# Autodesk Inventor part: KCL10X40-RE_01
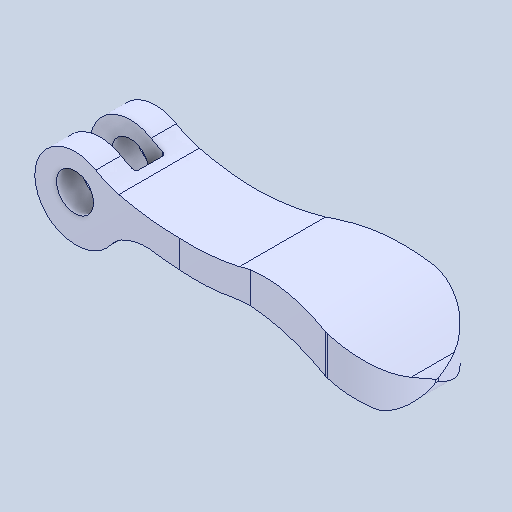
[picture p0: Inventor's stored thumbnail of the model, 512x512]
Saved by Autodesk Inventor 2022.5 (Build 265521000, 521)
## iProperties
Created: 2024-08
Part Number: KCL10X40-RE_01
Material: 一般
Document SubType Name: Modeling
Designer: ImaoCorp
Density: 1 g/cm^3
Appearance: 既定
Author: ImaoCorp
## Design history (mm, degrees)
feature "KCL10X40-RE_01"
node "ソリッド1"
